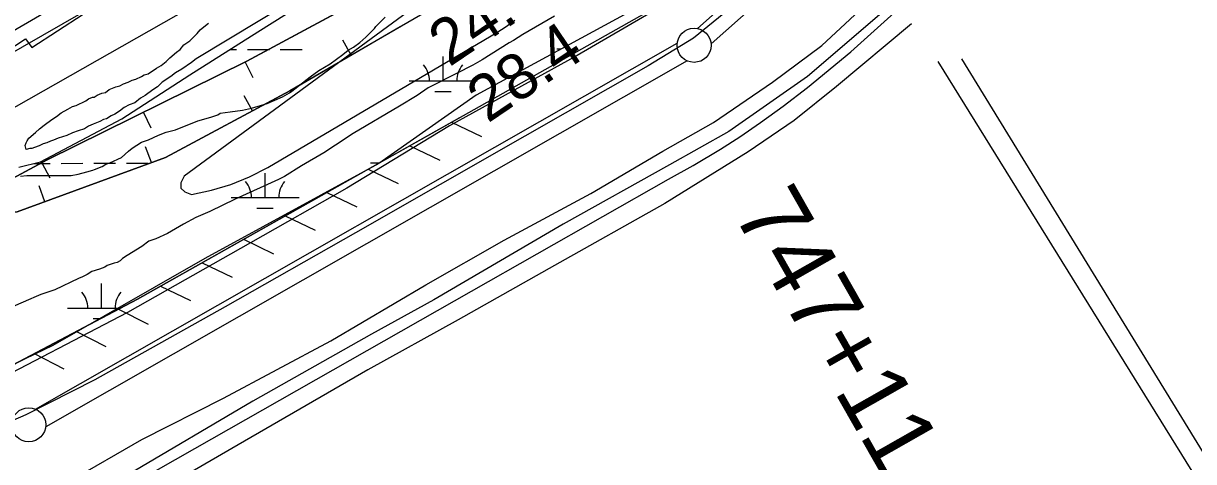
# Model space of a CAD drawing. Extents: x 3329297 to 3367176, y 649250 to 674653.
# Drawn here: x 3339828 to 3341544, y 658917 to 659560 of the extents above; entities that cross this region are included whole.
import ezdxf

# ---------------------------------------------------------------- set-up
doc = ezdxf.new("R2010")
doc.units = 0
for name, color, linetype in [('V-BORW-LINE', 7, 'Continuous'), ('V-FLOD-BASE', 7, 'Continuous'), ('V-LEVE-TOET', 7, 'Continuous'), ('V-RIVR-EDGE', 7, 'Continuous'), ('V-RIVR-RANG', 7, 'Continuous'), ('V-RIVR-RANG-IDEN', 7, 'Continuous'), ('V-ROAD-CNTR', 7, 'Continuous'), ('V-RRAP-FSHR', 7, 'Continuous'), ('V-RRAP-RVMT', 7, 'Continuous'), ('V-SITE-VEGE', 7, 'Continuous'), ('V-SURV-IDEN', 7, 'Continuous'), ('V-SURV-LINE', 7, 'Continuous'), ('V-TOPO-MAJR', 7, 'Continuous'), ('V-TOPO-MINR', 7, 'Continuous'), ('V-TOPO-SHOR', 7, 'Continuous'), ('V-UTIL-LINE', 7, 'Continuous'), ('V-WETL-SWMP', 7, 'Continuous')]:
    doc.layers.add(name, color=color, linetype=linetype)

msp = doc.modelspace()

# ---------------------------------------------------------------- linework, layer by layer
at = {"layer": 'V-BORW-LINE'}
for p, q in [((3340308.7, 659513.6), (3340296.1, 659535.3)), ((3340153, 659503.2), (3340164.1, 659480.7)), ((3340163.6, 659431.8), (3340151.7, 659453.8)), ((3340003.7, 659429.3), (3340014.7, 659406.9)), ((3340015.6, 659355.7), (3340007, 659379.1)), ((3339854.5, 659355.2), (3339866.3, 659333.2)), ((3339859.2, 659298.2), (3339850.6, 659321.7))]:
    msp.add_line(p, q, dxfattribs=at)
for points in [[(3340710, 659746.4), (3340218.4, 659461.3), (3340036.2, 659363.2), (3339818.3, 659283.2), (3339702, 659273.6), (3339862.6, 659359.6), (3340155.5, 659504.4), (3340403, 659638.3), (3340689.3, 659815.7), (3340830.7, 659916.8), (3340994.6, 660045.1), (3340822.4, 659849.8), (3340710, 659746.4)], [(3340349.2, 659609.2), (3340155.5, 659504.4), (3339862.6, 659359.6), (3339702, 659273.6), (3339818.3, 659283.2), (3340036.2, 659363.2), (3340218.4, 659461.3), (3340380.6, 659555.4)]]:
    msp.add_lwpolyline(points, dxfattribs=at)
at = {"layer": 'V-FLOD-BASE'}
msp.add_lwpolyline([(3342370.9, 661076), (3342282.2, 660901.4), (3342239.3, 660819.9), (3342233.1, 660810.3), (3342208.2, 660783), (3342060.1, 660649.2), (3341871.2, 660478.5), (3341712.7, 660336.5), (3341554.8, 660196.6), (3341394.9, 660052.6), (3341283.3, 659950.8), (3341091, 659780.9), (3340897.3, 659609.5), (3340810.5, 659538.6), (3340744.4, 659497.7), (3340563.4, 659394.3), (3340315, 659252.7), (3340123.7, 659143.8), (3339932.4, 659037), (3339831.2, 658985.3), (3339444.7, 658816.9)], dxfattribs=at)
at = {"layer": 'V-LEVE-TOET'}
for points in [[(3342310.8, 661081.7), (3342223.6, 660914.7), (3342194.5, 660857.9), (3342184.1, 660842.1), (3342164.1, 660820.3), (3342008.4, 660686.5), (3341889.9, 660585.5), (3341742.4, 660447.6), (3341613.6, 660334.4), (3341453.7, 660189), (3341280.1, 660034.7), (3341134, 659903), (3341003, 659787.7), (3340860.4, 659661.4), (3340813.5, 659618.4), (3340783.9, 659597.3), (3340640.1, 659512.9), (3340453, 659409.5), (3340302.3, 659318.3), (3340160.6, 659238), (3339980.3, 659135.9), (3339764.3, 659023.1)], [(3339896, 658888.7), (3340001.3, 658949.3), (3340121, 659009.8), (3340278.5, 659094.1), (3340418.2, 659176.5), (3340533.1, 659241.8), (3340660.3, 659310.5), (3340765.6, 659372.4), (3340839.9, 659414.6), (3340926.6, 659473.9), (3340998.9, 659527.7), (3341081.6, 659604.9), (3341230.5, 659742.8), (3341344.9, 659843.1), (3341442, 659918.8), (3341524, 659991.1), (3341625.3, 660080.5)]]:
    msp.add_lwpolyline(points, dxfattribs=at)
at = {"layer": 'V-RIVR-EDGE'}
msp.add_spline([(3339019.2, 659209.1), (3339040.6, 659221), (3339047.5, 659220.2), (3339051.4, 659224.1), (3339059.6, 659229.9), (3339065, 659232.2), (3339077, 659233.3), (3339080.9, 659237.6), (3339089.1, 659244.6), (3339098.4, 659252.3), (3339113.6, 659260.4), (3339145, 659276.6), (3339157, 659282), (3339163.7, 659286.3), (3339172.6, 659292.1), (3339185.4, 659290.9), (3339191.6, 659293.6), (3339202.9, 659300.1), (3339221.9, 659309.4), (3339243.2, 659321.4), (3339262.3, 659330.2), (3339276.2, 659336.4), (3339290.2, 659339.9), (3339299.5, 659339.4), (3339313.5, 659340.2), (3339322.8, 659343.3), (3339327.1, 659347.1), (3339337.5, 659350.2), (3339352.7, 659355.6), (3339373.6, 659366), (3339388.8, 659373.3), (3339417.9, 659386.1), (3339427.2, 659388.8), (3339436.9, 659389.1), (3339445.8, 659391.8), (3339449, 659393.8), (3339449.3, 659396.5), (3339452.5, 659399.6), (3339476.5, 659410.4), (3339483.1, 659410.3), (3339495.5, 659411.5), (3339507.2, 659412.6), (3339514.9, 659417.2), (3339525, 659424.6), (3339534, 659428.4), (3339548.3, 659432.7), (3339571.2, 659438.8), (3339586.4, 659441.9), (3339606.9, 659452.3), (3339621.3, 659455), (3339633.7, 659456.5), (3339638, 659458.4), (3339652.3, 659466.2), (3339674.1, 659475), (3339698.2, 659487.4), (3339709, 659492), (3339711, 659495.5), (3339713.7, 659501.7), (3339716.4, 659503.2), (3339729.2, 659504), (3339738.1, 659507.4), (3339746.7, 659512.5), (3339753.3, 659519.4), (3339759.9, 659524.8), (3339777.4, 659538.8), (3339798.8, 659557.7), (3339808.5, 659566.2), (3339812.4, 659572.4), (3339816.3, 659579.4), (3339820.9, 659584), (3339833, 659594.5), (3339856.7, 659610.7), (3339878.4, 659626.5), (3339902.1, 659642.4), (3339921.6, 659654.3), (3339930.9, 659657.8), (3339939.4, 659663.2), (3339958.1, 659673.3), (3339971.6, 659682.5), (3339983.3, 659691.4), (3339994.2, 659698.8), (3340008.9, 659705.7), (3340028, 659716.1), (3340043.1, 659723.5), (3340052.8, 659728.9), (3340059, 659735.1), (3340064.5, 659739.3), (3340071.9, 659743.9), (3340078.4, 659744.7), (3340088.5, 659749.3), (3340097.5, 659755.1), (3340109.1, 659764.8), (3340116.5, 659771.8), (3340123.1, 659782.2), (3340129, 659790.7), (3340139.9, 659802), (3340149.6, 659809.7), (3340155, 659812.8), (3340164.7, 659814.3), (3340172.9, 659814.3), (3340181.8, 659816.6), (3340189.6, 659821.6), (3340200.8, 659831.3), (3340212.9, 659843.3), (3340224.5, 659855.6), (3340233.1, 659861.4), (3340240.5, 659863), (3340244.7, 659863), (3340249, 659866.8), (3340254, 659868.8), (3340262.2, 659870.3), (3340276.2, 659871.8), (3340297.1, 659874.9), (3340308, 659879.5), (3340324.7, 659888.7), (3340329, 659894.9), (3340333.6, 659897.3), (3340340.6, 659898.8), (3340352.2, 659901.9), (3340361.6, 659908.8), (3340362.3, 659911.5), (3340362.7, 659914.6), (3340360.8, 659921.2), (3340362, 659922.8), (3340365.9, 659924.3), (3340377.9, 659931.3), (3340386.1, 659934.7), (3340405.5, 659941.7), (3340419.8, 659945.5), (3340433.8, 659950.9), (3340441.2, 659957.1), (3340445.1, 659961.7), (3340454.8, 659973.4)], degree=3, dxfattribs=at)
at = {"layer": 'V-ROAD-CNTR'}
msp.add_lwpolyline([(3338647.3, 658121.1), (3338841.9, 658234.5), (3339644.6, 658688.8), (3340485.2, 659167.2), (3340773.9, 659331.5), (3340810.3, 659351.5), (3340850.5, 659375.4), (3340878.6, 659393.7), (3340909, 659414.5), (3340942.4, 659438.6), (3340978, 659465.8), (3341041.4, 659518.3), (3341246.7, 659703.2), (3341943.9, 660321.4), (3342315.6, 660652)], dxfattribs=at)
at = {"layer": 'V-RRAP-FSHR'}
for p, q in [((3340455.5, 659414.9), (3340499.6, 659393.8)), ((3340394.6, 659380.5), (3340438.6, 659359.5)), ((3340333.6, 659346.2), (3340377.6, 659325.1)), ((3340272.6, 659311.8), (3340316.6, 659290.7)), ((3340211.6, 659277.4), (3340255.7, 659256.3)), ((3340150.6, 659243.1), (3340194.7, 659222)), ((3340089.7, 659208.7), (3340133.7, 659187.6)), ((3340028.7, 659174.3), (3340072.7, 659153.2)), ((3339967.3, 659140.7), (3340010.7, 659118.4)), ((3339905.4, 659108), (3339948.8, 659085.7)), ((3339843.5, 659075.3), (3339886.9, 659053))]:
    msp.add_line(p, q, dxfattribs=at)
msp.add_lwpolyline([(3340467.3, 659421.5), (3339994.8, 659155.2), (3339741.9, 659021.7), (3339700.9, 659003.9)], dxfattribs=at)
at = {"layer": 'V-RRAP-RVMT'}
for p, q in [((3339840.1, 659524.7), (3339959.1, 659602.5)), ((3339724.9, 659468.3), (3339830.7, 659537.6)), ((3339830.7, 659537.6), (3339840.1, 659524.7))]:
    msp.add_line(p, q, dxfattribs=at)
at = {"layer": 'V-SITE-VEGE'}
for points in [[(3340313.6, 659648.4), (3340081.1, 659508), (3340074.2, 659502.5), (3340060.3, 659492.9), (3340050.6, 659487.4), (3340043.7, 659481.9), (3340031.2, 659473.6), (3340024.2, 659466.8), (3340017.3, 659462.7), (3340006.2, 659454.4), (3339999.3, 659450.3), (3339990.9, 659443.4), (3339982.6, 659440.7), (3339975.7, 659436.6), (3339968.8, 659431.1), (3339961.8, 659427), (3339956.3, 659424.2), (3339949.4, 659420.1), (3339945.2, 659418.8), (3339939.7, 659416), (3339930, 659411.9), (3339923, 659409.2), (3339917.5, 659405.1), (3339907.8, 659402.3), (3339899.5, 659399.6), (3339891.2, 659395.5), (3339878.7, 659391.4), (3339871.8, 659388.7), (3339867.6, 659387.3), (3339862.1, 659384.6), (3339856.5, 659383.2), (3339851, 659380.5), (3339844.1, 659377.8), (3339839.9, 659376.4), (3339837.1, 659376.4), (3339831.6, 659375.1), (3339830.3, 659380.6), (3339831.7, 659384.7), (3339833.1, 659387.5), (3339835.8, 659391.6), (3339845.6, 659399.9), (3339851.1, 659405.4), (3339858.1, 659410.9), (3339869.2, 659419.1), (3339876.1, 659423.2), (3339883, 659428.7), (3339892.7, 659434.2), (3339899.7, 659438.3), (3339905.2, 659439.7), (3339919.1, 659446.5), (3339923.2, 659449.3), (3339928.8, 659452), (3339931.5, 659452), (3339935.7, 659454.7)], [(3340606.9, 659570.6), (3340560.5, 659543.7), (3340546.9, 659534.8), (3340540.1, 659531.4), (3340500.5, 659506.8), (3340486.9, 659498.9), (3340463.2, 659486.6), (3340421.3, 659465.4), (3340405.4, 659454.2), (3340379.4, 659438.5), (3340311.5, 659398.2), (3340285.4, 659381.4), (3340268.5, 659370.2), (3340235.6, 659351.2), (3340210.7, 659335.5), (3340201.7, 659331), (3340138.3, 659302), (3340101, 659284.1), (3340080.7, 659275.2), (3340062.5, 659265.1), (3340038.8, 659251.7), (3340021.8, 659243.8), (3340011.6, 659240.5), (3340001.4, 659232.6), (3339979.9, 659219.2), (3339973.1, 659214.7), (3339969.7, 659211.3), (3339965.2, 659209.1), (3339960.7, 659208), (3339950.5, 659204.7), (3339947.1, 659202.4), (3339939.2, 659199.1), (3339927.9, 659195.7), (3339921.1, 659191.3), (3339914.3, 659187.9), (3339908.7, 659185.7), (3339873.6, 659168.9), (3339853.2, 659162.2), (3339843.1, 659157.8), (3339838.5, 659155.5), (3339812.5, 659144.4)], [(3339935.7, 659454.7), (3339942.6, 659457.5), (3339948.2, 659458.8), (3339953.7, 659463), (3339963.4, 659467.1), (3339968.9, 659468.4), (3339974.5, 659471.2), (3339981.4, 659473.9), (3339987, 659476.6), (3339992.5, 659478), (3340000.8, 659482.1), (3340005, 659484.8), (3340010.5, 659486.2), (3340023, 659494.4), (3340029.9, 659498.5), (3340036.9, 659504), (3340042.4, 659509.5), (3340052.1, 659517.8), (3340057.7, 659521.9), (3340063.2, 659528.8), (3340071.6, 659534.3), (3340082.7, 659545.3), (3340086.9, 659550.8), (3340092.4, 659554.9), (3340099.3, 659560.4)], [(3340025.8, 659395.9), (3340037.1, 659400.3), (3340050.6, 659403.6), (3340083.4, 659417), (3340102.6, 659422.6), (3340112.8, 659425.9), (3340116.2, 659428.2), (3340130.9, 659430.3), (3340149, 659432.5), (3340162.5, 659435.8), (3340185.1, 659442.5), (3340207.7, 659452.5), (3340217.9, 659458.1), (3340221.3, 659460.4), (3340248.5, 659481.7), (3340261, 659490.7), (3340277.9, 659500.7), (3340296.1, 659514.2), (3340304, 659520.9), (3340311.9, 659525.4), (3340321, 659532.1), (3340330.1, 659540), (3340342.5, 659552.4), (3340344.8, 659555.7), (3340358.4, 659569.2)], [(3339823.4, 659335.9), (3339832.5, 659337), (3339897.9, 659336.6), (3339908.1, 659338.9), (3339920.5, 659342.2), (3339929.6, 659344.4), (3339931.8, 659345.5), (3339943.1, 659350), (3339948.8, 659353.3), (3339954.5, 659355.6), (3339971.4, 659363.4), (3339981.6, 659372.4), (3339987.3, 659376.9), (3340000.9, 659385.8), (3340011, 659389.2), (3340025.8, 659395.9)]]:
    msp.add_lwpolyline(points, dxfattribs=at)
at = {"layer": 'V-SURV-LINE'}
for points in [[(3340816.6, 659552.4), (3342192.4, 660772.9)], [(3342212.3, 660750.4), (3340836.5, 659530)], [(3339845.4, 658993.8), (3340786.8, 659531)], [(3340801.6, 659505), (3339860.3, 658967.8)]]:
    msp.add_lwpolyline(points, dxfattribs=at)
for centre in [(3340811.6, 659527.9), (3339835.5, 658970.9)]:
    msp.add_circle(centre, 25, dxfattribs=at)
at = {"layer": 'V-TOPO-MAJR'}
for points in [[(3339680.3, 659361), (3340365.3, 659750.5), (3340385.8, 659762.3), (3340406.1, 659774.4), (3340426.3, 659786.8), (3340446.3, 659799.3), (3340473.4, 659816.6), (3340479.9, 659820.7), (3340486.3, 659824.7), (3340492.8, 659828.6), (3340499.3, 659832.6), (3340505.8, 659836.5), (3340512.2, 659840.5), (3340518.6, 659844.7), (3340524.8, 659849), (3340704.3, 659974.9), (3340798.7, 660044.1), (3340891.1, 660115.8), (3340980.4, 660191.3), (3341067.7, 660269.3), (3341562.9, 660730.9)], [(3340431.5, 659606.9), (3340063.4, 659335.7), (3340058.8, 659326), (3340058.5, 659318), (3340064.4, 659312.7), (3340074.4, 659309), (3340103.7, 659315.2), (3340132.1, 659323.5), (3340159.4, 659335), (3340186, 659348.7), (3340522.3, 659546.8), (3340535.7, 659555.5), (3340548.6, 659565)]]:
    msp.add_lwpolyline(points, dxfattribs=at)
at = {"layer": 'V-TOPO-MINR'}
for points in [[(3339554.7, 659399.4), (3340285, 659824.6)], [(3339425.4, 659295.7), (3340316.2, 659807.5)]]:
    msp.add_lwpolyline(points, dxfattribs=at)
at = {"layer": 'V-TOPO-SHOR'}
msp.add_line((3341169.3, 659504.1), (3341616.3, 658782.7), dxfattribs=at)
for points in [[(3342461.6, 660847.4), (3342423.6, 660789.9), (3342396.6, 660750.9), (3342385.6, 660738.6), (3342320.7, 660673), (3342222.2, 660582.9), (3342098.1, 660476.4), (3341990.6, 660377.4), (3341869.3, 660270.3), (3341722.5, 660140.6), (3341577.1, 660010.9), (3341415.1, 659867.5), (3341249, 659722.8), (3341087, 659575.4), (3340978.1, 659481.9), (3340862.5, 659401.4), (3340775.7, 659352.4), (3340619.5, 659265.3), (3340429.6, 659154.4), (3340338.1, 659104), (3340164, 659005.3), (3339981.6, 658897.8), (3339819.9, 658807.3)], [(3341130.7, 659559.6), (3341020.5, 659467.5), (3340958.5, 659417.7), (3340891, 659371.3), (3340768.5, 659295.7), (3340606.8, 659204.5), (3340465.7, 659124.9), (3340332.9, 659051.4), (3340142.9, 658941.2), (3339975, 658843.8), (3339803.7, 658745.8)], [(3341203.9, 659508), (3341639.3, 658798.1), (3341957.8, 658990.8)]]:
    msp.add_lwpolyline(points, dxfattribs=at)
at = {"layer": 'V-UTIL-LINE'}
msp.add_lwpolyline([(3337436.3, 658138.6), (3337672.9, 658222.1), (3337855, 658267.6), (3338200.8, 658391), (3338279.9, 658444.5), (3338979.1, 658701.8), (3339577.2, 658950.3), (3339741.9, 659021.7), (3339994.8, 659155.2), (3340766.6, 659590.2), (3341329.8, 660088.4), (3341632.2, 660358.8), (3342178.2, 660842.1), (3342515.8, 661504), (3342751.2, 661989.4), (3343057.2, 662738.8), (3343121.4, 662899.3), (3343150.6, 662991.8), (3343161.5, 663146), (3343214.5, 663762.7), (3343263.8, 664509.6)], dxfattribs=at)
at = {"layer": 'V-WETL-SWMP'}
for p, q in [((3340171.6, 659547.6), (3340310.3, 659635.5)), ((3340731.7, 659585.1), (3340491.9, 659454.9)), ((3340071.7, 659484.5), (3340171.6, 659547.6)), ((3340130.3, 659521.6), (3340140.5, 659521.6)), ((3340156.5, 659521.6), (3340188.5, 659521.7)), ((3340204.5, 659521.7), (3340236.5, 659521.8)), ((3340443.4, 659475.7), (3340443.3, 659511.7)), ((3340610.4, 659522.5), (3340616.5, 659522.5)), ((3339971.9, 659420), (3340071.7, 659484.5)), ((3340393.4, 659475.6), (3340493.4, 659475.8)), ((3340431.4, 659460.3), (3340455.4, 659460.3)), ((3340491.9, 659454.9), (3340349, 659354.6)), ((3339852.7, 659357), (3339971.9, 659420)), ((3339820.8, 659348.8), (3339852.7, 659357)), ((3339843.1, 659354.5), (3339866.9, 659354.6)), ((3339882.9, 659354.6), (3339914.9, 659354.7)), ((3339930.9, 659354.7), (3339962.9, 659354.8)), ((3339978.9, 659354.8), (3340010.9, 659354.8)), ((3340349, 659354.6), (3340094, 659214.8)), ((3340336.8, 659355.5), (3340350.3, 659355.5)), ((3340182.3, 659304.4), (3340182.2, 659340.4)), ((3340132.3, 659304.3), (3340232.3, 659304.5)), ((3340170.3, 659289), (3340194.3, 659289)), ((3340094, 659214.8), (3339870.7, 659087.3)), ((3339942.1, 659142.1), (3339942, 659178.1)), ((3339892.1, 659142), (3339966.8, 659142.2)), ((3339930.1, 659126.7), (3339939.7, 659126.7)), ((3339870.7, 659087.3), (3339765.4, 659036.6))]:
    msp.add_line(p, q, dxfattribs=at)
for centre, start, end in [((3340388.1, 659476.1), 359.3365, 40.8801), ((3340498.6, 659476.3), 139.3365, 180.8801), ((3340127, 659304.8), 359.3365, 40.8801), ((3340237.5, 659305), 139.3365, 180.8801), ((3339886.9, 659142.5), 359.3365, 40.8801), ((3339997.4, 659142.7), 139.3365, 180.8801)]:
    msp.add_arc(centre, 35.2, start, end, dxfattribs=at)

# ---------------------------------------------------------------- texts
at = {"layer": 'V-RIVR-RANG'}
for s, p in [('24.4', (3340452.5, 659495.4)), ('28.4', (3340508.8, 659412.8))]:
    msp.add_text(s, height=67, rotation=34.1383, dxfattribs=at).set_placement(p)
at = {"layer": 'V-RIVR-RANG-IDEN'}
msp.add_text('D-070', height=83, rotation=309.7358, dxfattribs=at).set_placement((3341516.4, 659723.4))
at = {"layer": 'V-SURV-IDEN'}
msp.add_text('747+11.2', height=100, rotation=299.6169, dxfattribs=at).set_placement((3340867.5, 659282.4))

doc.saveas('drawing.dxf')
